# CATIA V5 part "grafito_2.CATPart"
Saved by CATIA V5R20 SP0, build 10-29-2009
Part number: grafito_2
Revision: ANY
Definition: UNKNOWN
Nomenclature: grafito
Source: Unknown
Bounding box of the stored display mesh (mm): x -2.498 to 2.428, y 2.038 to 22.006, z -2.5 to 2.5
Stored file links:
  C:\Users\Utente\Desktop\IO LAVORO\3D X SITO CF\CUMSA\3D files SD\SD 4528\grafito_2.CATPart
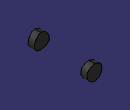
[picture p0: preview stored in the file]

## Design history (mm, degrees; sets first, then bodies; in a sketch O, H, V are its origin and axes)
Body1 "Saliente-Extruir1" (main body)
  Solid1: solid without history
Body2 "Saliente-Extruir1"
  Solid2: solid without history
